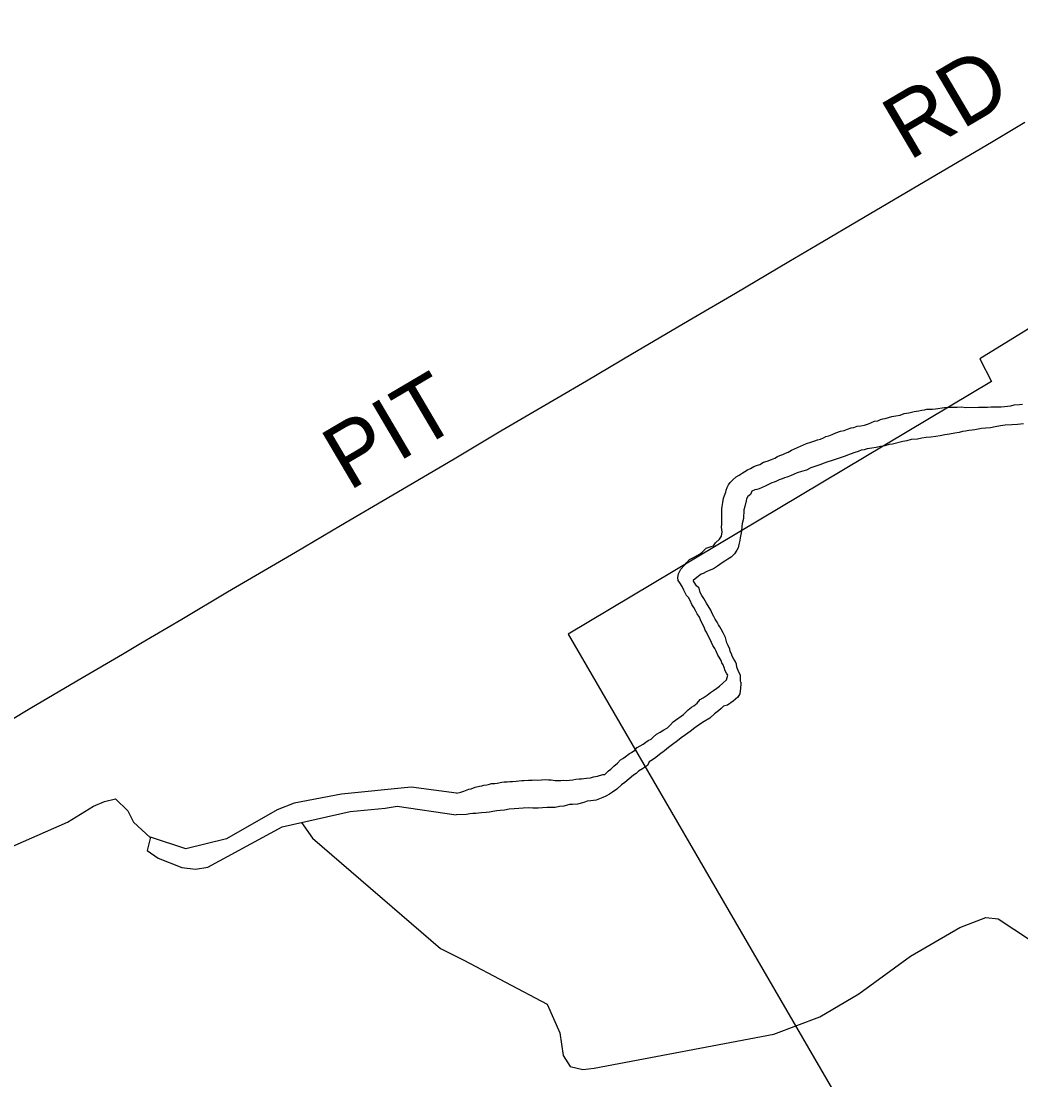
# Model space of a CAD drawing. Extents: x -19.5 to 44.1, y 0 to 22.
# Drawn here: x -15.096 to -14.206, y 3.404 to 4.346 of the extents above; entities that cross this region are included whole.
import ezdxf

# ---------------------------------------------------------------- set-up
doc = ezdxf.new("R2010")
doc.units = 0
for name, color, linetype in [('GM_X_County_Road', 7, 'Continuous'), ('GM_X_County_Road_Text', 7, 'Continuous'), ('GM_X_Minor_River', 7, 'Continuous'), ('GM_X_Township', 7, 'Continuous')]:
    doc.layers.add(name, color=color, linetype=linetype)

msp = doc.modelspace()

# ---------------------------------------------------------------- linework, layer by layer
at = {"layer": 'GM_X_County_Road'}
msp.add_lwpolyline([(-15.12923, 3.71013), (-15.08706, 3.73526), (-15.04317, 3.7611), (-15.00621, 3.78283), (-14.98962, 3.79259), (-14.95321, 3.81405), (-14.91262, 3.83817), (-14.85205, 3.87368), (-14.81193, 3.8974), (-14.76533, 3.92481), (-14.71066, 3.95687), (-14.66896, 3.98155), (-14.6191, 4.01073), (-14.59279, 4.02608), (-14.55169, 4.05056), (-14.49755, 4.08229), (-14.46001, 4.10429), (-14.4124, 4.13239), (-14.38728, 4.14729), (-14.34605, 4.17156), (-14.30271, 4.19716), (-14.27598, 4.213), (-14.23202, 4.23874), (-14.20212, 4.25655)], dxfattribs=at)
at = {"layer": 'GM_X_Minor_River'}
for points in [[(-14.32063, 3.99456), (-14.31721, 3.9949), (-14.31341, 3.99562), (-14.3096, 3.9971), (-14.30542, 3.99781), (-14.30086, 3.9989), (-14.29668, 3.99961), (-14.29401, 3.99996), (-14.29173, 4.00031), (-14.28945, 4.00105), (-14.28717, 4.00102), (-14.28452, 4.00099), (-14.28186, 4.00134), (-14.27958, 4.0017), (-14.27578, 4.00203), (-14.27388, 4.00239), (-14.27008, 4.00273), (-14.26667, 4.00269), (-14.2625, 4.00265), (-14.2587, 4.00298), (-14.25491, 4.00256), (-14.24352, 4.00281), (-14.23973, 4.00277), (-14.23555, 4.00272), (-14.23214, 4.00306), (-14.22682, 4.003), (-14.22341, 4.00297), (-14.22037, 4.00331), (-14.21771, 4.00366), (-14.21467, 4.00401), (-14.21163, 4.00473), (-14.20707, 4.00506), (-14.20441, 4.00541)], [(-14.48247, 3.79578), (-14.48396, 3.79846), (-14.48582, 3.80227), (-14.48694, 3.80419), (-14.48767, 3.8061), (-14.48841, 3.808), (-14.49027, 3.81144), (-14.49101, 3.81335), (-14.49213, 3.81564), (-14.49399, 3.8187), (-14.49548, 3.82176), (-14.49697, 3.82444), (-14.49883, 3.82712), (-14.50032, 3.83055), (-14.50181, 3.83323), (-14.50368, 3.83515), (-14.50591, 3.83973), (-14.50739, 3.84317), (-14.50964, 3.84623), (-14.51113, 3.84853), (-14.51148, 3.85119), (-14.51069, 3.85422), (-14.50991, 3.85612), (-14.50875, 3.85838), (-14.50529, 3.86214), (-14.50337, 3.8644), (-14.50107, 3.86704), (-14.49687, 3.86927), (-14.49458, 3.87038), (-14.49153, 3.87225), (-14.48962, 3.87374), (-14.48616, 3.87712), (-14.4816, 3.87859), (-14.47969, 3.87933), (-14.47777, 3.88197), (-14.47432, 3.88535), (-14.47239, 3.88799), (-14.47197, 3.89178), (-14.47231, 3.89596), (-14.47228, 3.89862), (-14.47225, 3.90166), (-14.47223, 3.90356), (-14.4722, 3.90622), (-14.47216, 3.90926), (-14.47213, 3.9123), (-14.47173, 3.91419), (-14.47132, 3.91799), (-14.47052, 3.92178), (-14.46973, 3.92405), (-14.46856, 3.92708), (-14.46816, 3.92897), (-14.46738, 3.93124), (-14.46622, 3.93351), (-14.46468, 3.93577), (-14.46238, 3.93802), (-14.45931, 3.94065), (-14.45664, 3.94214), (-14.45397, 3.94401), (-14.45167, 3.9455), (-14.44938, 3.947), (-14.44671, 3.94811), (-14.44366, 3.94997), (-14.44137, 3.95071), (-14.43833, 3.95181), (-14.43489, 3.95367), (-14.43184, 3.95478), (-14.42804, 3.95626), (-14.42499, 3.95736), (-14.42269, 3.95885), (-14.42041, 3.95959), (-14.41774, 3.9607), (-14.41545, 3.96181), (-14.41317, 3.96255), (-14.41012, 3.96441), (-14.39677, 3.97034), (-14.39297, 3.97144), (-14.38916, 3.97291), (-14.38687, 3.97365), (-14.38421, 3.97438), (-14.38154, 3.97549), (-14.37963, 3.97661), (-14.37697, 3.97734), (-14.37392, 3.97844), (-14.37049, 3.97992), (-14.3663, 3.9814), (-14.36326, 3.98212), (-14.36021, 3.98323), (-14.35679, 3.98433), (-14.35451, 3.98468), (-14.35146, 3.98579), (-14.34842, 3.98613), (-14.345, 3.98686), (-14.34157, 3.98796), (-14.3389, 3.98907), (-14.33623, 3.99018), (-14.33319, 3.99052), (-14.33091, 3.99164), (-14.32862, 3.99237), (-14.32672, 3.99273), (-14.32368, 3.99345), (-14.32063, 3.99456)], [(-14.20346, 3.98792), (-14.20878, 3.98722), (-14.21371, 3.9869), (-14.21979, 3.98659), (-14.22397, 3.98626), (-14.22853, 3.98517), (-14.23271, 3.98445), (-14.23689, 3.98412), (-14.24069, 3.98378), (-14.24373, 3.98306), (-14.24677, 3.98271), (-14.24905, 3.98236), (-14.25209, 3.98201), (-14.25513, 3.98129), (-14.25779, 3.98094), (-14.26083, 3.98021), (-14.26464, 3.97949), (-14.2692, 3.97878), (-14.27338, 3.97807), (-14.27756, 3.97736), (-14.28136, 3.97664), (-14.28592, 3.97593), (-14.2901, 3.9756), (-14.2939, 3.97526), (-14.2977, 3.97417), (-14.3034, 3.97385), (-14.3072, 3.97275), (-14.31101, 3.97204), (-14.32013, 3.96986), (-14.32317, 3.96951), (-14.32698, 3.96842), (-14.33078, 3.9677), (-14.33458, 3.96698), (-14.33839, 3.96626), (-14.34257, 3.96555), (-14.34523, 3.96482), (-14.34789, 3.96447), (-14.35056, 3.96336), (-14.3536, 3.96226), (-14.35779, 3.96078), (-14.36312, 3.95894), (-14.36846, 3.9571), (-14.37379, 3.95526), (-14.37874, 3.9538), (-14.38178, 3.95269), (-14.38407, 3.95158), (-14.38826, 3.95011), (-14.39283, 3.94864), (-14.39664, 3.94678), (-14.40121, 3.94532), (-14.40502, 3.94422), (-14.40769, 3.94311), (-14.41112, 3.94163), (-14.41416, 3.94052), (-14.41645, 3.93979), (-14.41835, 3.93905), (-14.42102, 3.93794), (-14.42331, 3.93683), (-14.42559, 3.93609), (-14.4275, 3.93535), (-14.4294, 3.93462), (-14.43131, 3.9335), (-14.4336, 3.93238), (-14.43627, 3.93127), (-14.43893, 3.93016), (-14.44084, 3.92943), (-14.44274, 3.92907), (-14.44541, 3.92796), (-14.44658, 3.92493), (-14.44887, 3.92306), (-14.45003, 3.92117), (-14.45043, 3.91927), (-14.45162, 3.91435), (-14.45241, 3.91132), (-14.45287, 3.90372), (-14.45406, 3.89918), (-14.45447, 3.89652), (-14.45451, 3.89272), (-14.4553, 3.88932)], [(-14.4553, 3.88932), (-14.45571, 3.88628), (-14.45612, 3.88401), (-14.45691, 3.8806), (-14.4577, 3.87756), (-14.45887, 3.8753), (-14.46079, 3.87228), (-14.46386, 3.86928), (-14.46692, 3.86741), (-14.46959, 3.86554), (-14.47188, 3.86405), (-14.47609, 3.86105), (-14.47953, 3.85881), (-14.48334, 3.85734), (-14.48601, 3.85623), (-14.48868, 3.85474), (-14.49058, 3.854), (-14.49441, 3.851), (-14.49755, 3.84854)], [(-14.4553, 3.75773), (-14.45554, 3.759), (-14.45549, 3.76394), (-14.45772, 3.76815), (-14.45883, 3.7712), (-14.45918, 3.77386), (-14.46029, 3.77653), (-14.46141, 3.77845), (-14.4629, 3.78112), (-14.46364, 3.78303), (-14.46475, 3.78532), (-14.46511, 3.78723), (-14.46659, 3.79066), (-14.4677, 3.79295), (-14.46879, 3.79753), (-14.47103, 3.80173), (-14.47289, 3.80517), (-14.47401, 3.80708), (-14.47512, 3.80899), (-14.47624, 3.81129), (-14.47811, 3.81397), (-14.47922, 3.81626), (-14.48071, 3.81894), (-14.48181, 3.82199), (-14.48592, 3.82811), (-14.48704, 3.8304), (-14.48816, 3.83232), (-14.49002, 3.835), (-14.49151, 3.83767), (-14.49223, 3.84148), (-14.49486, 3.84379), (-14.49673, 3.84685), (-14.49755, 3.84854)], [(-14.70854, 3.65889), (-14.70473, 3.65999), (-14.70207, 3.66072), (-14.69749, 3.66256), (-14.69559, 3.66292), (-14.69178, 3.6644), (-14.68798, 3.66512), (-14.68608, 3.66547), (-14.68418, 3.66621), (-14.68152, 3.66656), (-14.67924, 3.66692), (-14.67733, 3.66766), (-14.6743, 3.66762), (-14.6724, 3.66798), (-14.66822, 3.66869), (-14.66593, 3.66905), (-14.66328, 3.66902), (-14.661, 3.66937), (-14.65872, 3.66935), (-14.6553, 3.66969), (-14.65302, 3.67004), (-14.65036, 3.67039), (-14.64847, 3.67037), (-14.64429, 3.6707), (-14.64126, 3.67067), (-14.63898, 3.67102), (-14.6367, 3.67062), (-14.63291, 3.67096), (-14.62949, 3.6713), (-14.62645, 3.67088), (-14.62418, 3.67086), (-14.62077, 3.67044), (-14.61887, 3.67042), (-14.61546, 3.67038), (-14.61318, 3.67073), (-14.61015, 3.67032), (-14.60787, 3.67067), (-14.60483, 3.67102), (-14.60217, 3.67137), (-14.59913, 3.67172), (-14.59723, 3.67169), (-14.59495, 3.67205), (-14.59267, 3.6724), (-14.58925, 3.67274), (-14.58659, 3.67347), (-14.58469, 3.67383), (-14.58279, 3.67419), (-14.57822, 3.67566), (-14.57632, 3.67564), (-14.57325, 3.67902), (-14.57096, 3.68052), (-14.56827, 3.68315), (-14.56521, 3.68577), (-14.56252, 3.68878), (-14.56023, 3.68989), (-14.55832, 3.69139), (-14.5545, 3.69439), (-14.55259, 3.69513), (-14.54953, 3.69737), (-14.54761, 3.69963), (-14.54494, 3.70112), (-14.54227, 3.70261), (-14.53997, 3.70448), (-14.53768, 3.70598), (-14.53501, 3.70709), (-14.53347, 3.70897), (-14.53041, 3.71159), (-14.52698, 3.71346), (-14.52392, 3.71532), (-14.52049, 3.71718), (-14.5178, 3.71981), (-14.5155, 3.72244), (-14.50632, 3.72918), (-14.50402, 3.73144), (-14.5021, 3.73331), (-14.49904, 3.73556), (-14.49713, 3.73668), (-14.49407, 3.7393), (-14.49138, 3.74231), (-14.48871, 3.7438), (-14.48527, 3.74642), (-14.48221, 3.74867), (-14.47953, 3.75053), (-14.47648, 3.7524), (-14.47418, 3.75427), (-14.47112, 3.7569), (-14.46805, 3.7599), (-14.46687, 3.76407), (-14.46799, 3.76598), (-14.46911, 3.7679), (-14.47021, 3.77094), (-14.47095, 3.77323), (-14.47206, 3.77515), (-14.4728, 3.77705), (-14.47467, 3.78012), (-14.47579, 3.78203), (-14.47727, 3.78546), (-14.47838, 3.78776), (-14.48025, 3.79044), (-14.48136, 3.79311), (-14.48247, 3.79578)], [(-14.4553, 3.75773), (-14.45519, 3.75634), (-14.45561, 3.75254), (-14.45604, 3.74761), (-14.45797, 3.74459), (-14.46218, 3.74084), (-14.46715, 3.73748), (-14.47058, 3.73638), (-14.47287, 3.7345), (-14.47518, 3.73225), (-14.47862, 3.72963), (-14.48283, 3.72588), (-14.48779, 3.72289), (-14.492, 3.72028), (-14.4962, 3.71729), (-14.50041, 3.71392), (-14.50462, 3.71093), (-14.50844, 3.70831), (-14.5115, 3.70568), (-14.51609, 3.70232), (-14.51953, 3.6997), (-14.52336, 3.6967), (-14.52757, 3.69333), (-14.53101, 3.69071), (-14.53406, 3.68884), (-14.53674, 3.68697), (-14.5383, 3.68357), (-14.54288, 3.68058), (-14.54631, 3.67872), (-14.54861, 3.67647), (-14.55091, 3.67497), (-14.55856, 3.6686), (-14.56162, 3.66636), (-14.56583, 3.6626), (-14.56966, 3.65999), (-14.57233, 3.65812), (-14.57539, 3.65625), (-14.57805, 3.65514), (-14.58415, 3.65293), (-14.58871, 3.65222), (-14.59213, 3.65188), (-14.59517, 3.65078), (-14.60088, 3.64932), (-14.60506, 3.64899), (-14.60772, 3.64902), (-14.61, 3.64828), (-14.61304, 3.64756), (-14.61684, 3.64722), (-14.62065, 3.64612), (-14.62406, 3.64616), (-14.62785, 3.6462), (-14.63203, 3.64587)], [(-14.70854, 3.65889), (-14.749, 3.66423), (-14.811, 3.65807), (-14.85326, 3.65001), (-14.86816, 3.64417), (-14.91336, 3.61831), (-14.94956, 3.6094), (-14.98128, 3.61977), (-14.98413, 3.60805), (-14.97437, 3.60106), (-14.95325, 3.59275), (-14.94112, 3.59142), (-14.93009, 3.59314), (-14.86385, 3.62892), (-14.80328, 3.64276), (-14.77211, 3.64569), (-14.76145, 3.64742), (-14.7088, 3.63964)], [(-15.53019, 3.5424), (-15.45618, 3.56845), (-15.43526, 3.57116), (-15.36757, 3.60274), (-15.34469, 3.60883), (-15.33407, 3.60866), (-15.32389, 3.60432), (-15.30365, 3.58881), (-15.27118, 3.60159), (-15.26002, 3.6109), (-15.22904, 3.6256), (-15.2076, 3.61349), (-15.16663, 3.58854), (-15.15332, 3.59023), (-15.05508, 3.63309), (-15.03207, 3.64753), (-15.02214, 3.65155), (-15.01223, 3.65405), (-15.0014, 3.64325), (-14.99625, 3.63329), (-14.98134, 3.61953)], [(-14.63203, 3.64587), (-14.63583, 3.64553), (-14.64038, 3.64558), (-14.64417, 3.64601), (-14.64911, 3.64568), (-14.65291, 3.64535), (-14.65708, 3.64501), (-14.66164, 3.64469), (-14.66582, 3.64397), (-14.66962, 3.64363), (-14.67266, 3.64329), (-14.67608, 3.64257), (-14.67912, 3.64222), (-14.68216, 3.64188), (-14.68633, 3.64154), (-14.68899, 3.64119), (-14.69127, 3.64084), (-14.69393, 3.64087), (-14.69659, 3.64052), (-14.69963, 3.64017), (-14.7088, 3.63964)], [(-14.84652, 3.63288), (-14.83668, 3.619), (-14.72288, 3.52076), (-14.70213, 3.51018)], [(-14.70213, 3.51018), (-14.62779, 3.47122), (-14.6165, 3.44558), (-14.61344, 3.42539), (-14.60717, 3.41578), (-14.59585, 3.41292), (-14.58598, 3.41426), (-14.42591, 3.44438), (-14.3847, 3.45996), (-14.35023, 3.48022), (-14.30416, 3.51394), (-14.26013, 3.53933), (-14.23685, 3.5484), (-14.22589, 3.54707), (-14.16933, 3.50958), (-14.14998, 3.48948), (-14.13798, 3.4828), (-14.10731, 3.43819), (-14.10375, 3.4256), (-14.10678, 3.40401), (-14.13854, 3.32294)]]:
    msp.add_lwpolyline(points, dxfattribs=at)
at = {"layer": 'GM_X_Township'}
msp.add_lwpolyline([(-12.58005, 5.0285), (-13.29879, 4.61052), (-13.76027, 4.34215), (-14.07444, 4.14922), (-14.24226, 4.04593), (-14.23196, 4.02565), (-14.60903, 3.8006), (-14.24604, 3.17588), (-14.71778, 2.90569), (-15.04161, 2.70723), (-14.98832, 2.61287), (-14.95906, 2.56107)], dxfattribs=at)

# ---------------------------------------------------------------- texts
at = {"layer": 'GM_X_County_Road_Text'}
for s, rotation, p in [('RD', 30.54075, (-14.30555, 4.22165)), ('PIT', 30.52784, (-14.80451, 3.9276))]:
    msp.add_text(s, height=0.056818, rotation=rotation, dxfattribs=at).set_placement(p)

doc.saveas('drawing.dxf')
